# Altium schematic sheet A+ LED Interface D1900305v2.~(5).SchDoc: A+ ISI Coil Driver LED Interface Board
size A; Address2: California Institute of; Address3: Technology; DocumentNumber: D1900305; Revision: v2; SheetNumber: 1; SheetTotal: 1; PageSetup: Record=PageOptions¦CenterHorizontal=True¦CenterVertical=True¦PrintScale=1.38¦XCorrection=1.00¦YCorrection=1.00¦PrintKind=1¦BorderSize=5000000¦LeftOffset=0¦BottomOffset=0¦Orientation=2¦PaperLength=1000¦PaperWidth=1000¦Scale=100¦PaperSource=15¦PrintQuality=600¦MediaType=1¦DitherType=10¦PaperKind=11x17¦PrintScaleMode=1
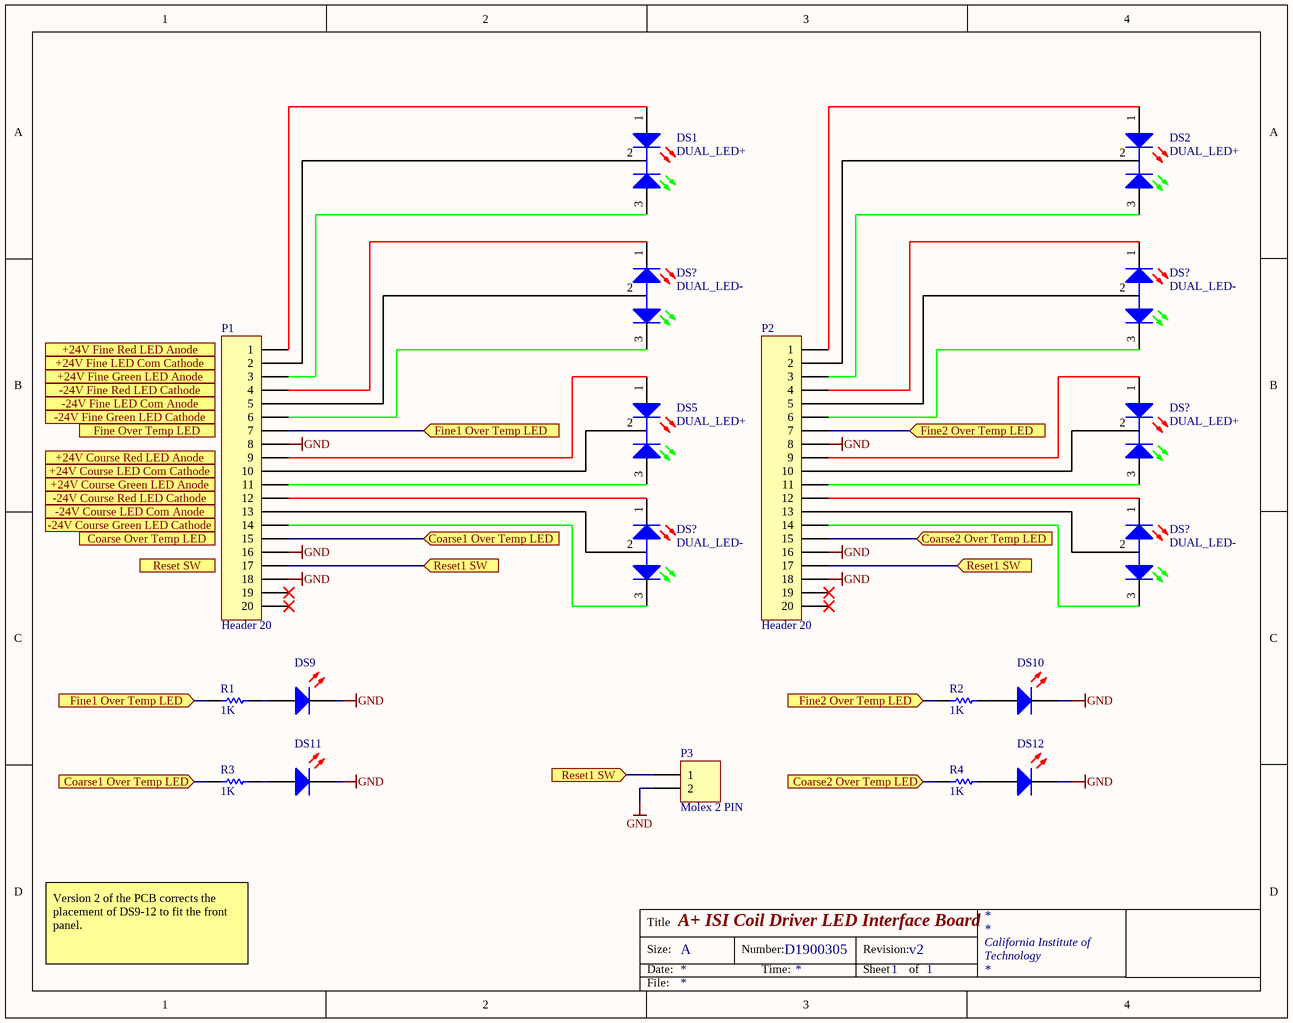
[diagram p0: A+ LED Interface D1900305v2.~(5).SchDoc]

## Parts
(Parts that share a designator on the sheet are numbered #1, #2 ... from top to bottom, then left to right.)
DS1  DUAL_LED+  [COM_CATHODE LED]
DS2  DUAL_LED+  [COM_CATHODE LED]
DS5  DUAL_LED+  [COM_CATHODE LED]
DS9  LED0  [RED_led]  (value not drawn)
DS10  LED0  [RED_led]  (value not drawn)
DS11  LED0  [RED_led]  (value not drawn)
DS12  LED0  [RED_led]  (value not drawn)
DS?#1  DUAL_LED-  [COM_ANODE LED]
DS?#2  DUAL_LED-  [COM_ANODE LED]
DS?#3  DUAL_LED+  [LED R/G COMM CATHODE (-)]
DS?#4  DUAL_LED-  [COM_ANODE LED]
DS?#5  DUAL_LED-  [COM_ANODE LED]
P1  Header 20  [IDC 20 _Vertical]
P2  Header 20  [IDC 20 _Vertical]
P3  Molex 2 PIN  [2Pin_Molex 100 mil]
R1  1K  [3216[1206]]
R2  1K  [3216[1206]]
R3  1K  [3216[1206]]
R4  1K  [3216[1206]]

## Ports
+24V Course Green LED Anode, +24V Course LED Com Cathode, +24V Course Red LED Anode, +24V Fine Green LED Anode, +24V Fine LED Com Cathode, +24V Fine Red LED Anode, -24V Course Green LED Cathode, -24V Course LED Com Anode, -24V Course Red LED Cathode, -24V Fine Green LED Cathode, -24V Fine LED Com Anode, -24V Fine Red LED Cathode, Coarse1 Over Temp LED (in), Coarse2 Over Temp LED (in), Coarse Over Temp LED, Fine1 Over Temp LED (in), Fine2 Over Temp LED (in), Fine Over Temp LED, Reset1 SW (in), Reset SW

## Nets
GND: DS9.2(K) DS10.2(K) DS11.2(K) DS12.2(K) P1.8 P1.16 P1.18 P2.8 P2.16 P2.18 P3.2
Coarse1 Over Temp LED: P1.15 R3.1 ; port Coarse1 Over Temp LED
Coarse2 Over Temp LED: P2.15 R4.1 ; port Coarse2 Over Temp LED
Fine1 Over Temp LED: P1.7 R1.1 ; port Fine1 Over Temp LED
Fine2 Over Temp LED: P2.7 R2.1 ; port Fine2 Over Temp LED
Reset1 SW: P1.17 P2.17 P3.1 ; port Reset1 SW
NetDS1_1: DS1.1(A) P1.1
NetDS1_2: DS1.2(K) P1.2
NetDS1_3: DS1.3(A) P1.3
NetDS2_1: DS2.1(A) P2.1
NetDS2_2: DS2.2(K) P2.2
NetDS2_3: DS2.3(A) P2.3
NetDS5_1: DS5.1(A) P1.9
NetDS5_2: DS5.2(K) P1.10
NetDS5_3: DS5.3(A) P1.11
NetDS9_1: DS9.1(A) R1.2
NetDS10_1: DS10.1(A) R2.2
NetDS11_1: DS11.1(A) R3.2
NetDS12_1: DS12.1(A) R4.2
NetDS?#1_1: DS?#1.1(A) P1.4
NetDS?#1_2: DS?#1.2(K) P1.5
NetDS?#1_3: DS?#1.3(A) P1.6
NetDS?#2_1: DS?#2.1(A) P2.4
NetDS?#2_2: DS?#2.2(K) P2.5
NetDS?#2_3: DS?#2.3(A) P2.6
NetDS?#3_1: DS?#3.1(A) P2.9
NetDS?#3_2: DS?#3.2(K) P2.10
NetDS?#3_3: DS?#3.3(A) P2.11
NetDS?#4_1: DS?#4.1(A) P1.12
NetDS?#4_2: DS?#4.2(K) P1.13
NetDS?#4_3: DS?#4.3(A) P1.14
NetDS?#5_1: DS?#5.1(A) P2.12
NetDS?#5_2: DS?#5.2(K) P2.13
NetDS?#5_3: DS?#5.3(A) P2.14

Not connected (* = marked no-connect by the designer): P1 19* 20*; P2 19* 20*

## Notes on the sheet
- Version 2 of the PCB corrects the placement of DS9-12 to fit the front panel.

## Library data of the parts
DS1 DS2 DS5 = DUAL_LED+: Green, Red  LED Indication - Discrete 2.2V Green, 2V Red Radial - 3 Leads; Manufacturer: Lumex; Manufacturer Part Number: SSL-LX3059IGW; Lens Color: White; Viewing Angle: 60°; Test Current: 20mA; Lens Style: Dome,Round,Diffused,Colorless; Luminous Intensity: 30mcd; Lens Transparency: Diffused; Dominant Wavelength: 635nm; Forward Current: 150mA; Power Dissipation: 105mW; Wavelength: 565nm; Number of LEDs: 2
DS9-DS12 = LED0: Red 640nm LED Indication - Discrete 1.85V Radial; Manufacturer: Kingbright; Manufacturer Part Number: WP710A10SRD/F; Lens Style: Dome,Diffused; Viewing Angle: 40°; Luminous Intensity: 160mcd; Test Current: 20mA; Lens Transparency: Diffused
DS?#1 DS?#2 DS?#4 DS?#5 = DUAL_LED Comm Anode: Green, Red  LED Indication - Discrete 2.2V Green, 2V Red Radial - 3 Leads; Manufacturer: Lumex; Manufacturer Part Number: SSL-LX3059IGW-CA; Forward Current: 20mA; Luminous Intensity: 30mcd; Lens Style: Dome,Diffused,Colorless; Viewing Angle: 60°; Wavelength: 635nm; Number of LEDs: 2
DS?#3 = DUAL_LED Comm Cathode: Green, Red  LED Indication - Discrete 2.2V Green, 2V Red Radial - 3 Leads; Manufacturer: Lumex; Manufacturer Part Number: SSL-LX3059IGW; Lens Color: White; Viewing Angle: 60°; Test Current: 20mA; Lens Style: Dome,Round,Diffused,Colorless; Luminous Intensity: 30mcd; Lens Transparency: Diffused; Dominant Wavelength: 635nm; Forward Current: 150mA; Power Dissipation: 105mW; Wavelength: 565nm; Number of LEDs: 2
P1 P2 = Header 20: Header, 20-Pin; Manufacturer: Amphenol FCI; Manufacturer Part Number: 71918-120LF; Current Rating: 1A; Mating Cycles: 250; Number of Poles: 20; Voltage Rating: 1.5kV; Insulation Resistance: 100GR; Gender: Male; Connector Type: Male Pin; Pitch: 2.54mm; Contact Post Length: 2.9mm; Row Spacing: 0.1inch; Hole Diameter: 1mm; Approvals: UL,CSA
P3 = Header 2H: Header, 2-Pin, Right Angle; Number of Positions: 2; Gender: Male; Contact Resistance: 10mR; Current Rating: 4A; Voltage Rating: 250V; Max Current Rating: 7A; Insulation Resistance: 50GR; Pitch: 2.54mm; Approvals: UL,CSA
R1-R4 = Res Semi: Semiconductor Resistor; Manufacturer: Panasonic; Manufacturer Part Number: ERJ-8ENF1001V; Resistance: 1kR; Tolerance: 1%; Voltage Rating: 200V; Power Rating: 250mW; Temperature Coefficient: 100ppm/°C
